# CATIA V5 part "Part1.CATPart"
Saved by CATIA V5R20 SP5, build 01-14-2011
Part number: Bielle L
Bounding box of the stored display mesh (mm): x -110 to 10, y -60 to 10, z -17 to 17
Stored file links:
  U:\CFAO\Thinkmotion\Part1.CATPart
  U:\CFAO\Thinkmotion\Bras Articule.CATProduct
  U:\CFAO\Thinkmotion\Squelette Bielle L.CATPart
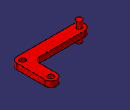
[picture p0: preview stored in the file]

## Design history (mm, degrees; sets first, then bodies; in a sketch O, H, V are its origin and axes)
Set1
  Plane1: linked copy from another document
  Point1: linked copy from another document
  Line1: linked copy from another document
  Line2: linked copy from another document
  Point2: linked copy from another document
  Point3: linked copy from another document
Body1 (main body)
  Sketch1 on Plane1, origin (0, 0, 0), H (1, 0, 0), V (0, -1, 0)
    line L1 (-100, 40) -> (-10, 40)
    line L2 (-10, 40) -> (-10, 0)
    point P3 (-10, 0)
    arc A1 centre (0, 0) radius 10 from (-10, 0) to (10, 0) ccw
    line L3 (10, 0) -> (10, 60)
    line L4 (10, 60) -> (-100, 60)
    arc A2 centre (-100, 50) radius 10 from (-100, 60) to (-100, 40) ccw
    reference projected line E1 (-100, 50) -> (0, 50) from Line1
    reference projected line E2 (0, 0) -> (0, 50) from Line2
    reference projected point E3 (-100, 50) from Point2
    reference projected point E4 (0, 0) from Point3
    radius A1 = 10
    radius A2 = 10
    horizontal: L1 H, L4 H
    coincidence: P3 H
    vertical: L2 V
    tangency: A1 L2, L3 A1, A2 L1, A2 L4
    symmetry: L1 L4 E1, L2 L3 E2
    concentricity: A2 E3, A1 E4
  Pad1: profile Sketch1, direction (0, 0, -1), length 5, mirrored extent
  Fillet1: radius 10, on edge [face of Pad1 from Sketch1.L2 | face of Pad1 from Sketch1.L1]; edge [face of Pad1 from Sketch1.L4 | face of Pad1 from Sketch1.L3]
  Sketch2 on start face of Pad1, origin (0, 0, 5), H (1, 0, 0), V (0, 1, 0)
    circle A1 centre (0, 0) radius 5
    circle A2 centre (0, -50) radius 5
    point P1 (0, -50)
    reference projected arc E1 centre (0, 0) radius 10 from (10, 0) to (-10, 0) ccw from edge [start face of Pad1 | face of Pad1 from Sketch1.A1]
    reference projected arc E2 centre (0, -50) radius 10 from (0, -60) to (10, -50) ccw from edge [start face of Pad1 | face of Fillet1]
    radius A1 = 5
    radius A2 = 5
    coincidence: P1 V
    concentricity: A1 E1, A2 E2
  Pocket1: profile Sketch2, direction (0, 0, -1), through (limit type 6)
  Sketch3 on Plane1, origin (0, 0, 0), H (1, 0, 0), V (0, -1, 0)
    circle A1 centre (-100, 50) radius 5
    reference projected point E1 (-100, 50) from axis of face of Pad1 from Sketch1.A2
    radius A1 = 5
    concentricity: A1 E1
  Pad2: profile Sketch3, direction (0, 0, -1), length 17, mirrored extent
